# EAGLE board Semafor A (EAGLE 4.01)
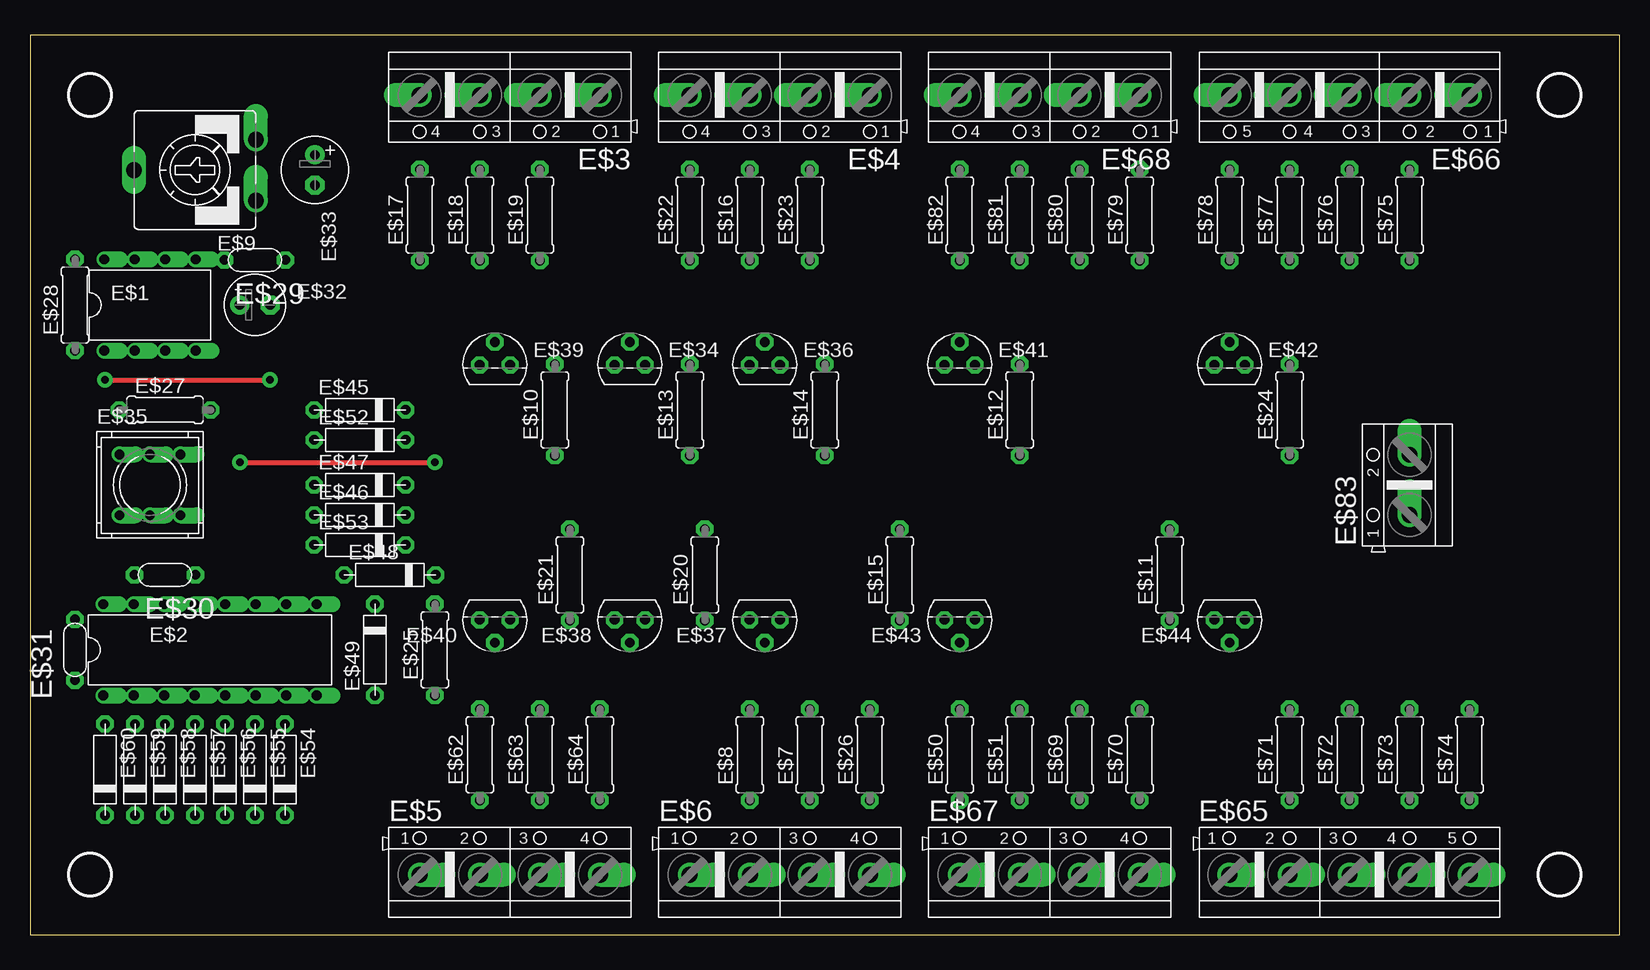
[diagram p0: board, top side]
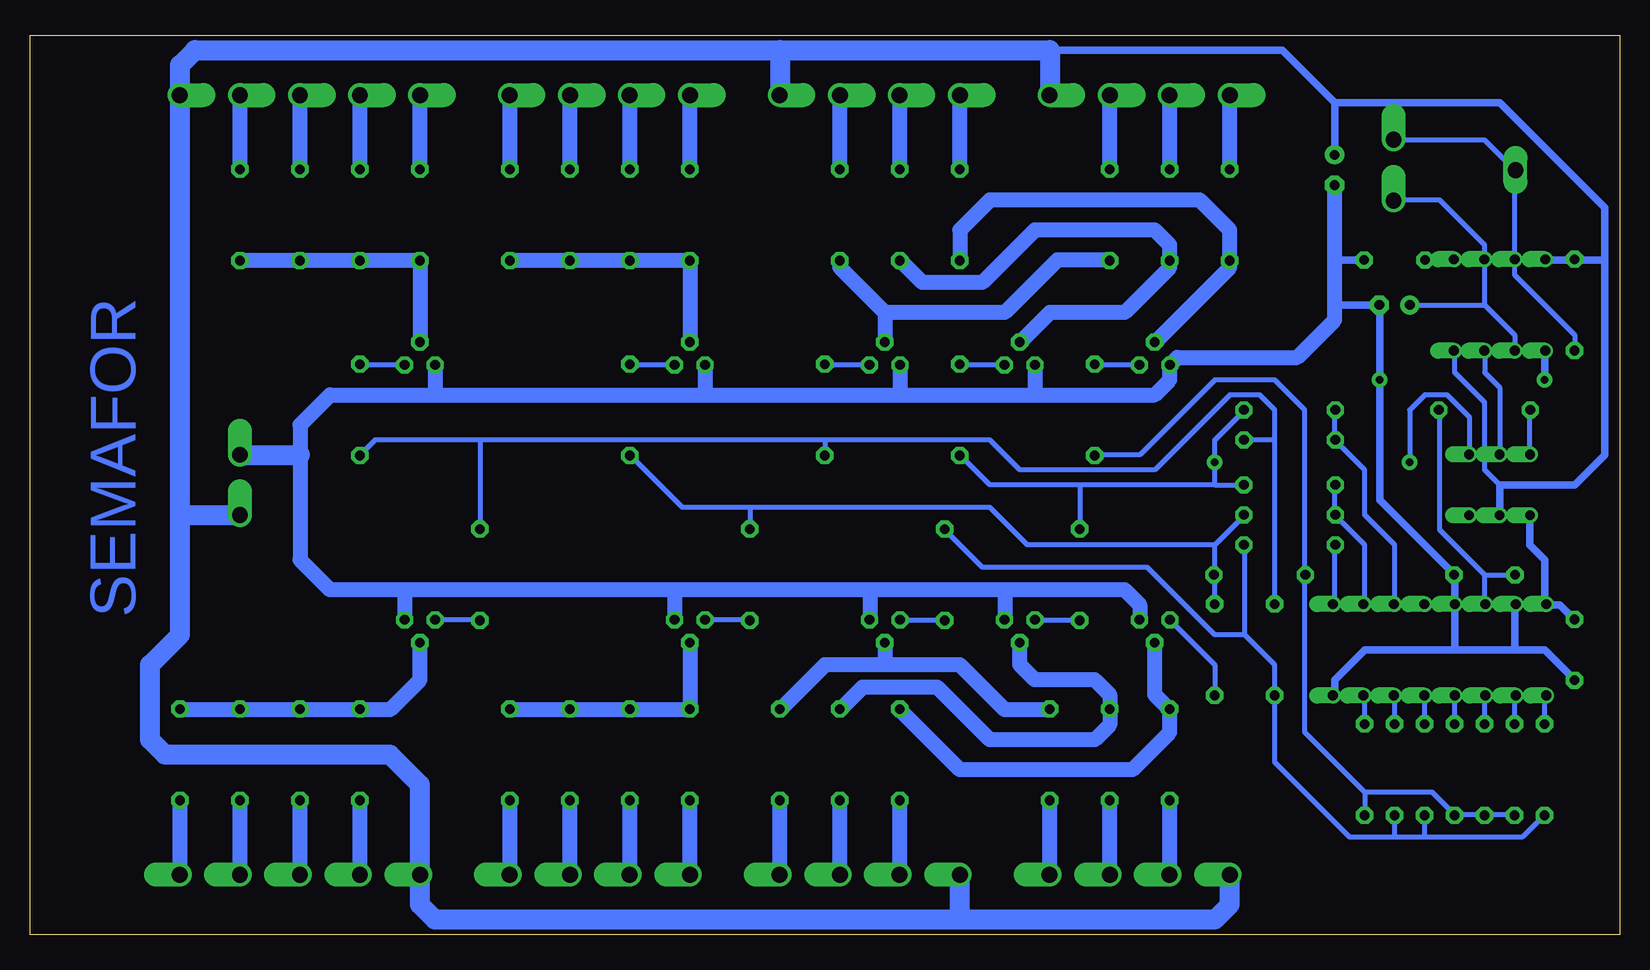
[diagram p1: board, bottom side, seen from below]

Size 132.5 x 75 mm. Coordinates in mm from the lower left corner, seen from the top.
Outline: 0,0 132.5,0 132.5,75 0,75 0,0
Copper layers used: Top, Bottom

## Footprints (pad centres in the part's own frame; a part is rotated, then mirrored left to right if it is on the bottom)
DIL-08 = drill 0.813 offset: 1 -3.81,-3.81; 2 -1.27,-3.81; 3 1.27,-3.81; 4 3.81,-3.81; 5 3.81,3.81; 6 1.27,3.81; 7 -1.27,3.81; 8 -3.81,3.81
DIL-16 = drill 0.813 offset: 1 -8.89,-3.81; 2 -6.35,-3.81; 3 -3.81,-3.81; 4 -1.27,-3.81; 5 1.27,-3.81; 6 3.81,-3.81; 7 6.35,-3.81; 8 8.89,-3.81; 9 8.89,3.81; 10 6.35,3.81; 11 3.81,3.81; 12 1.27,3.81; 13 -1.27,3.81; 14 -3.81,3.81; 15 -6.35,3.81; 16 -8.89,3.81
AK500/4 = drill 1.321 offset: 1 -7.518,0; 2 -2.489,0; 3 2.489,0; 4 7.518,0
0207/7 = drill 0.813 pad 1.422 octagon: 1 -3.81,0; 2 3.81,0
CA9V = drill 1.321 offset: 1 -2.54,-5.08; 3 2.54,-5.08 | drill 1.321 long: 2 0,5.08
C05A = drill 0.813 pad 1.422 octagon: P$1 -2.54,0; P$2 2.54,0
E2,5-5 = drill 0.813 pad 1.6 round: + -1.27,0 | drill 0.813 pad 1.6 octagon: - 1.27,0
E2,5-6 = drill 0.813 pad 1.6 round: + -1.27,0 | drill 0.813 pad 1.6 octagon: - 1.27,0
TO92C = drill 0.813 pad 1.422 octagon: B 1.27,0; C 0,1.905; E -1.27,0
9077-2 = drill 0.813 offset: 1 -2.54,2.54; 2 0,2.54; 3 2.54,2.54; 4 -2.54,-2.54; 5 0,-2.54; 6 2.54,-2.54
1N4148/7 = drill 0.813 pad 1.422 octagon: P$1 -3.81,0; P$2 3.81,0
AK500/5 = drill 1.321 offset: 1 -10.033,0; 2 -5.004,0; 3 0,0; 4 5.004,0; 5 10.008,0
AK500/2 = drill 1.321 offset: 1 -2.515,0; 2 2.515,0

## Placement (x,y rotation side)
E$1  [DIL-08]  10,52.5 0 top
E$2  [DIL-16]  15,23.75 0 top
E$3  [AK500/4]  40,70 180 top
E$4  [AK500/4]  62.5,70 180 top
E$5  [AK500/4]  40,5 0 top
E$6  [AK500/4]  62.5,5 0 top
E$7  [0207/7]  65,15 90 top
E$8  [0207/7]  60,15 90 top
E$9  [CA9V]  13.75,63.75 90 top
E$10  [0207/7]  43.75,43.75 90 top
E$11  [0207/7]  95,30 90 top
E$12  [0207/7]  82.5,43.75 90 top
E$13  [0207/7]  55,43.75 90 top
E$14  [0207/7]  66.25,43.75 90 top
E$15  [0207/7]  72.5,30 90 top
E$16  [0207/7]  60,60 90 top
E$17  [0207/7]  32.5,60 90 top
E$18  [0207/7]  37.5,60 90 top
E$19  [0207/7]  42.5,60 90 top
E$20  [0207/7]  56.25,30 90 top
E$21  [0207/7]  45,30 90 top
E$22  [0207/7]  55,60 90 top
E$23  [0207/7]  65,60 90 top
E$24  [0207/7]  105,43.75 90 top
E$25  [0207/7]  33.75,23.75 90 top
E$26  [0207/7]  70,15 90 top
E$27  [0207/7]  11.25,43.75 0 top
E$28  [0207/7]  3.75,52.5 90 top
E$29  [C05A]  18.75,56.25 180 top
E$30  [C05A]  11.25,30 180 top
E$31  [C05A]  3.75,23.75 90 top
E$32  [E2,5-5]  18.75,52.5 0 top
E$33  [E2,5-6]  23.75,63.75 270 top
E$34  [TO92C]  50,47.5 0 top
E$35  [9077-2]  10,37.5 0 top
E$36  [TO92C]  61.25,47.5 0 top
E$37  [TO92C]  61.25,26.25 180 top
E$38  [TO92C]  50,26.25 180 top
E$39  [TO92C]  38.75,47.5 0 top
E$40  [TO92C]  38.75,26.25 180 top
E$41  [TO92C]  77.5,47.5 0 top
E$42  [TO92C]  100,47.5 0 top
E$43  [TO92C]  77.5,26.25 180 top
E$44  [TO92C]  100,26.25 180 top
E$45  [1N4148/7]  27.5,43.75 0 top
E$46  [1N4148/7]  27.5,35 0 top
E$47  [1N4148/7]  27.5,37.5 0 top
E$48  [1N4148/7]  30,30 0 top
E$49  [1N4148/7]  28.75,23.75 90 top
E$50  [0207/7]  77.5,15 90 top
E$51  [0207/7]  82.5,15 90 top
E$52  [1N4148/7]  27.5,41.25 0 top
E$53  [1N4148/7]  27.5,32.5 0 top
E$54  [1N4148/7]  21.25,13.75 270 top
E$55  [1N4148/7]  18.75,13.75 270 top
E$56  [1N4148/7]  16.25,13.75 270 top
E$57  [1N4148/7]  13.75,13.75 270 top
E$58  [1N4148/7]  11.25,13.75 270 top
E$59  [1N4148/7]  8.75,13.75 270 top
E$60  [1N4148/7]  6.25,13.75 270 top
E$62  [0207/7]  37.5,15 90 top
E$63  [0207/7]  42.5,15 90 top
E$64  [0207/7]  47.5,15 90 top
E$65  [AK500/5]  110,5 0 top
E$66  [AK500/5]  110,70 180 top
E$67  [AK500/4]  85,5 0 top
E$68  [AK500/4]  85,70 180 top
E$69  [0207/7]  87.5,15 90 top
E$70  [0207/7]  92.5,15 90 top
E$71  [0207/7]  105,15 90 top
E$72  [0207/7]  110,15 90 top
E$73  [0207/7]  115,15 90 top
E$74  [0207/7]  120,15 90 top
E$75  [0207/7]  115,60 90 top
E$76  [0207/7]  110,60 90 top
E$77  [0207/7]  105,60 90 top
E$78  [0207/7]  100,60 90 top
E$79  [0207/7]  92.5,60 90 top
E$80  [0207/7]  87.5,60 90 top
E$81  [0207/7]  82.5,60 90 top
E$82  [0207/7]  77.5,60 90 top
E$83  [AK500/2]  115,37.5 90 top

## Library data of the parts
E$1 E$2 = ic-package
E$3-E$6 E$65-E$68 E$83 = con-ptr500
E$7 E$8 E$10-E$33 E$50 E$51 E$62-E$64 E$69-E$82 = rcl
E$9 = pot
E$34 E$36-E$44 = transistor-small-signal
E$35 = switch-misc
E$45-E$49 E$52-E$60 = diode1

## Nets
S$63: E$65.3
S$72: E$66.3

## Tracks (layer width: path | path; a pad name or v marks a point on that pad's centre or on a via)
S$1
  Bottom 0.406: 6.25,17.5 6.25,20
S$2
  Bottom 0.406: 8.75,17.5 8.75,20
S$3
  Bottom 0.406: 11.25,17.5 11.25,20
S$4
  Bottom 0.406: 13.75,17.5 13.75,20
S$5
  Bottom 0.406: 16.25,17.5 16.25,20
S$6
  Bottom 0.406: 18.75,17.5 18.75,20
S$7
  Bottom 0.406: 21.25,17.5 21.25,20
S$8
  Bottom 0.406: 40,47.5 43.75,47.5
S$9
  Bottom 0.406: 37.5,26.25 33.75,22.5 33.75,20
S$10
  Bottom 0.406: 82.5,40 78.12,35.62 72.5,35.62 | 72.5,35.62 72.5,33.75 | 72.5,35.62 52.5,35.62 49.38,32.5 33.75,32.5 | 33.75,32.5 31.25,35 | 33.75,27.5 33.75,32.5
S$11
  Bottom 0.61: 3.75,26.25 5,27.5 6.25,27.5 6.25,31.25 7.5,32.5 7.5,35
S$12  (via drill 0.61 pad 1.27)
  Top 0.406: v6.25,46.25 v20,46.25
  Bottom 0.61: 23.75,52.5 20,52.5 v20,46.25 20,36.25 13.75,30 13.75,23.75 | 23.75,20 23.75,21.25 21.25,23.75 13.75,23.75 | 8.75,23.75 13.75,23.75 | 8.75,23.75 8.75,27.5 | 8.75,23.75 6.25,23.75 3.75,21.25 | v6.25,46.25 6.25,48.75
S$13
  Bottom 0.406: 11.25,30 8.75,30 | 11.25,27.5 11.25,30 | 11.25,30 15,33.75 15,43.75
S$14
  Bottom 0.406: 13.75,48.75 13.75,46.88 11.25,44.38 11.25,38.75 10,37.5
  Bottom 0.61: 23.75,69.38 23.75,65 | 23.75,69.38 10,69.38 1.25,60.62 1.25,56.25 | 10,35 10,37.5 3.75,37.5 1.25,40 1.25,56.25 | 1.25,56.25 6.25,56.25 | 47.5,73.75 28.12,73.75 23.75,69.38
  Bottom 1.676: 47.5,70 47.5,73.75 70,73.75 | 70,73.75 70,70 | 70,73.75 118.75,73.75 120,72.5 120,35 | 120,35 115,35 | 120,35 120,25 122.5,22.5 122.5,20.62 | 122.5,20.62 122.5,21.25 | 122.5,20.62 122.5,16.25 121.25,15 102.5,15 100,12.5 100,2.5 98.75,1.25 55,1.25 | 55,1.25 55,5 | 55,1.25 33.75,1.25 32.5,2.5 32.5,5
S$15
  Bottom 0.406: 18.75,61.25 15,61.25 11.25,57.5 11.25,52.5 | 17.5,52.5 11.25,52.5 | 11.25,52.5 8.75,50 8.75,48.75
S$16
  Bottom 0.406: 13.75,56.25 16.25,56.25
S$17
  Bottom 0.406: 18.75,66.25 11.25,66.25 8.75,63.75 8.75,55 3.75,50 3.75,48.75
S$18
  Bottom 0.406: 7.5,40 7.5,43.75
S$19
  Bottom 0.406: 11.25,48.75 11.25,46.88 10,45.62 10,40
S$21
  Bottom 0.406: 18.75,27.5 18.75,32.5 21.25,35 21.25,38.75 23.75,41.25 23.75,43.75
S$22
  Bottom 0.61: 21.25,56.25 23.75,56.25
  Bottom 1.27: 23.75,62.5 23.75,56.25 23.75,51.25 26.88,48.12 36.88,48.12 37.5,47.5 37.5,46.25 38.75,45 48.75,45 | 98.75,45 107.5,45 110,42.5 110,40 110,31.25 107.5,28.75 101.25,28.75 | 98.75,45 76.25,45 | 76.25,45 60,45 | 60,45 48.75,45 | 48.75,47.5 48.75,45 | 60,47.5 60,45 | 76.25,47.5 76.25,45 | 98.75,47.5 98.75,45 | 51.25,28.75 62.5,28.75 | 62.5,28.75 62.5,26.25 | 51.25,28.75 51.25,26.25 | 51.25,28.75 41.25,28.75 40,27.5 40,26.25 | 62.5,28.75 78.75,28.75 | 78.75,28.75 101.25,28.75 | 78.75,26.25 78.75,28.75 | 101.25,26.25 101.25,28.75
  Bottom 1.676: 115,40 110,40
S$23
  Bottom 0.406: 21.25,27.5 21.25,32.5 23.75,35 23.75,37.5
S$24
  Bottom 0.406: 45,37.5 45,33.75 | 31.25,43.75 33.75,41.25 33.75,37.5 | 33.75,37.5 31.25,37.5 | 55,40 52.5,37.5 45,37.5 | 33.75,37.5 45,37.5
S$25
  Bottom 0.406: 23.75,27.5 23.75,32.5
S$26
  Bottom 0.406: 31.25,25 31.25,32.5 | 31.25,25 28.75,22.5 28.75,14.38 22.5,8.12 18.75,8.12 | 18.75,8.12 18.75,10 | 16.25,8.12 18.75,8.12 | 16.25,8.12 16.25,10 | 16.25,8.12 8.12,8.12 6.25,10 | 56.25,33.75 53.12,30.62 39.38,30.62 33.75,25 31.25,25
S$27
  Bottom 1.27: 50,49.38 47.5,51.88 41.25,51.88 37.5,55.62 37.5,57.5 38.75,58.75 48.75,58.75 53.12,54.38 58.12,54.38 60,56.25
S$28
  Bottom 0.406: 60,26.25 56.25,26.25
S$29
  Bottom 0.406: 48.75,26.25 45,26.25
S$30
  Bottom 0.406: 21.25,11.88 21.25,10 | 21.25,11.88 26.25,16.88 26.25,43.75 28.75,46.25 33.75,46.25 40,40 43.75,40 | 21.25,11.88 15.62,11.88 13.75,10 8.75,10
S$31
  Bottom 0.406: 28.75,41.25 31.25,41.25 | 28.75,41.25 28.75,43.75 30,45 32.5,45 38.75,38.75 50,38.75 52.5,41.25 66.25,41.25 | 28.75,27.5 28.75,41.25 | 66.25,41.25 66.25,40 | 66.25,41.25 95,41.25 | 95,41.25 103.75,41.25 105,40 | 95,41.25 95,33.75
S$32
  Bottom 0.406: 51.25,47.5 55,47.5
S$33
  Bottom 0.406: 62.5,47.5 66.25,47.5
S$34
  Bottom 0.406: 101.25,47.5 105,47.5
S$35
  Bottom 0.406: 72.5,26.25 76.25,26.25
S$36
  Bottom 0.406: 78.75,47.5 82.5,47.5
S$37
  Bottom 1.27: 65,56.25 65,55.62 61.25,51.88 | 42.5,56.25 46.88,56.25 51.25,51.88 61.25,51.88 | 61.25,51.88 61.25,49.38
S$38
  Bottom 1.27: 50,24.38 50,22.5 48.75,21.25 43.75,21.25 42.5,20 42.5,17.5 43.75,16.25 52.5,16.25 56.88,20.62 63.12,20.62 65,18.75
S$39
  Bottom 1.27: 100,24.38 100,21.25 102.5,18.75 120,18.75
S$40
  Bottom 1.27: 32.5,63.75 32.5,70
S$41
  Bottom 1.27: 37.5,63.75 37.5,70
S$42
  Bottom 1.27: 42.5,64.38 42.5,70
S$43
  Bottom 1.27: 55,63.75 55,70
S$44
  Bottom 1.27: 60,63.75 60,70
S$45
  Bottom 1.27: 65,63.75 65,70
S$46
  Bottom 1.27: 38.75,49.38 32.5,55.62 32.5,58.75 35,61.25 52.5,61.25 55,58.75 55,56.25
S$48
  Bottom 1.27: 60,18.75 55,13.75 40.62,13.75 37.5,16.88 37.5,18.75 38.75,20 38.75,24.38
S$49
  Bottom 0.406: 95,26.25 98.75,26.25
S$50
  Bottom 1.27: 70,18.75 66.25,22.5 61.25,22.5 | 61.25,22.5 55,22.5 51.25,18.75 47.5,18.75 | 61.25,24.38 61.25,22.5
S$51
  Bottom 1.27: 37.5,5 37.5,11.25
S$52
  Bottom 1.27: 42.5,5 42.5,11.25
S$53
  Bottom 1.27: 47.5,5 47.5,11.25
S$54
  Bottom 1.27: 60,5 60,11.25
S$55
  Bottom 1.27: 65,5 65,11.25
S$56
  Bottom 1.27: 70,5 70,11.25
S$57  (via drill 0.61 pad 1.27)
  Top 0.406: v17.5,39.38 v33.75,39.38
  Bottom 0.406: v17.5,39.38 17.5,43.75 16.25,45 14.38,45 12.5,43.12 12.5,40
S$58
  Bottom 1.27: 77.5,5 77.5,11.25
S$59
  Bottom 1.27: 82.5,5 82.5,11.25
S$60
  Bottom 1.27: 87.5,5 87.5,11.25
S$61
  Bottom 1.27: 92.5,5 92.5,11.25
S$62
  Bottom 1.27: 105,5 105,11.25
S$63
  Bottom 1.27: E$65.3 110,11.25
S$64
  Bottom 1.27: 115,5 115,11.25
S$65
  Bottom 1.27: 120,5 120,11.25
S$66
  Bottom 1.27: 77.5,63.75 77.5,70
S$67
  Bottom 1.27: 82.5,63.75 82.5,70
S$68
  Bottom 1.27: 87.5,63.75 87.5,70
S$69
  Bottom 1.27: 92.5,63.75 92.5,70
S$70
  Bottom 1.27: 100,63.75 100,70
S$71
  Bottom 1.27: 105,63.75 105,70
S$72
  Bottom 1.27: 110,63.75 E$66.3
S$73
  Bottom 1.27: 115,63.75 115,70
S$74
  Bottom 1.27: 115,56.25 100,56.25 100,49.38
S$75
  Bottom 1.27: 92.5,56.25 77.5,56.25 77.5,49.38
S$76
  Bottom 1.27: 77.5,24.38 77.5,18.75 92.5,18.75

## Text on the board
Bottom: SEMAFOR
tValues: G | Y | R | G | Y | R | R | R | R | R | G | G | G | G | C4 | R9 | K1 | K2 | K5 | K6 | P1 | R13 | R15 | R17 | R14 | R16 | R18 | R25 | R26 | R27 | R28 | R29 | R30 | R31 | R32 | C3 | R1 | Ic1 | C1 | T1 | T2 | T3 | T7 | T8 | R2 | D14 | R3 | R4 | R5 | R9 | R10 | GND | D13 | D11 | K9 | S1 | D10 | D8 | C2 | D9 | R7 | R8 | R11 | R12 | +12V | T10 | C5 | R6 | T4 | T5 | T6 | T9 | Ic2 | D12 | D5 | D2 | D1 | D3 | D6 | D7 | D4 | R19 | R21 | R23 | R20 | R22 | R24 | R33 | R34 | R35 | R36 | R37 | R38 | R39 | R40 | K4 | K8 | K3 | K7 | R | Y | G | R | Y | G | G | G | G | G | R | R | R | R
